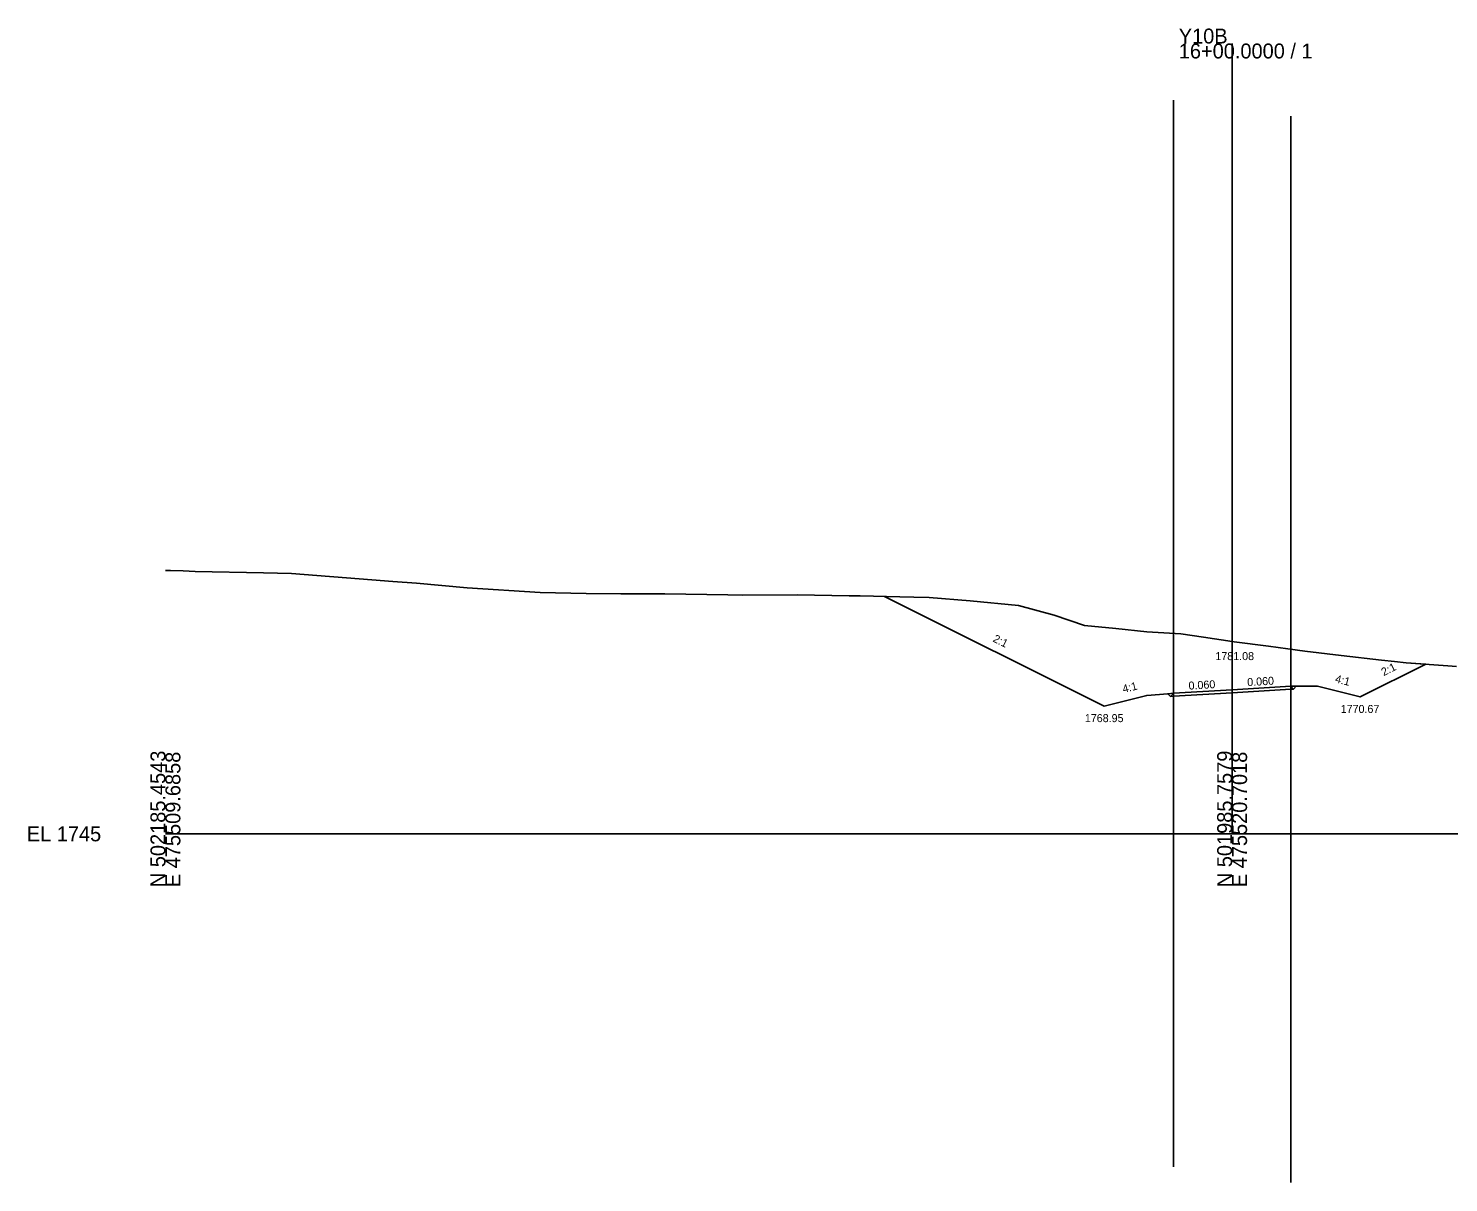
# Model space of a CAD drawing. Extents: x -26 to 1803, y -10 to 9558.
# Drawn here: x -25.7 to 240.6, y 5934.6 to 6151 of the extents above; entities that cross this region are included whole.
import ezdxf

# ---------------------------------------------------------------- set-up
doc = ezdxf.new("R2010")
doc.units = 0
for name, color, linetype in [('Exist Cross Section Cell', 7, 'Continuous'), ('Exist XS Center Line Elevation Label', 7, 'Continuous'), ('Exist XS Ground Line', 7, 'Continuous'), ('Prop XS Ditch Slope Text', 7, 'Continuous'), ('Prop XS Ditch Standard Text', 7, 'Continuous'), ('Prop XS Dump Level', 7, 'Continuous'), ('Prop XS Earthwork Shape', 7, 'Continuous'), ('Prop XS EOT Tick Mark', 7, 'Continuous'), ('Prop XS Finish Grade', 7, 'Continuous'), ('Prop XS Finish Grade Earthwork', 7, 'Continuous'), ('Prop XS Finish Grade Pavement', 7, 'Continuous'), ('Prop XS Hydro Typical Ditch Data', 7, 'Continuous'), ('Prop XS Pvmt Edge Slope', 7, 'Continuous'), ('Prop XS SE Text', 7, 'Continuous'), ('Prop XS Shoulder Borrow Shape', 7, 'Continuous'), ('Prop XS Side Slope Text', 7, 'Continuous'), ('Prop XS Subgrade Earthwork', 7, 'Continuous'), ('Scratch_Level_2', 7, 'Continuous')]:
    doc.layers.add(name, color=color, linetype=linetype)

msp = doc.modelspace()

# ---------------------------------------------------------------- linework, layer by layer
at = {"layer": 'Exist Cross Section Cell'}
for p, q in [((200, 6000), (200, 6148.21)), ((0, 6000), (200, 6000)), ((200, 6000), (400, 6000))]:
    msp.add_line(p, q, dxfattribs=at)
at = {"layer": 'Exist XS Ground Line'}
msp.add_lwpolyline([(0, 6049.4), (0.94, 6049.37), (3.32, 6049.34), (5.58, 6049.22), (18.36, 6048.95), (23.65, 6048.81), (38.73, 6047.61), (42.65, 6047.31), (47.09, 6046.98), (56.58, 6046.16), (70.27, 6045.28), (78.9, 6045.07), (85.36, 6045.01), (93.61, 6045.03), (105.48, 6044.84), (108.11, 6044.77), (118.45, 6044.8), (128.18, 6044.65), (130.28, 6044.65), (137.68, 6044.47), (140.3, 6044.41), (143.22, 6044.34), (150.91, 6043.69), (159.95, 6042.81), (166.66, 6040.98), (172.3, 6039.07), (178.22, 6038.5), (184.02, 6037.86), (190.38, 6037.48), (194.64, 6036.89), (200, 6036.08), (200.4, 6036.02), (206.83, 6035.22), (210.42, 6034.67), (213.62, 6034.26), (220.43, 6033.44), (228.04, 6032.6), (230.45, 6032.32), (232.61, 6032.1), (240.47, 6031.52), (242.1, 6031.37)], dxfattribs=at)
at = {"layer": 'Prop XS Dump Level'}
for p, q in [((189, 6026.35), (200, 6027.01)), ((200, 6027.01), (211, 6027.67))]:
    msp.add_line(p, q, dxfattribs=at)
at = {"layer": 'Prop XS Earthwork Shape'}
msp.add_lwpolyline([(232.61, 6032.1), (236.31, 6031.83), (224, 6025.67), (216, 6027.67), (212.02, 6027.67), (211.51, 6027.16), (211, 6027.13), (200, 6026.47), (189, 6025.81), (188.42, 6025.78), (187.93, 6026.27), (184, 6025.95), (176, 6023.95), (134.83, 6044.54), (137.68, 6044.47), (140.3, 6044.41), (143.22, 6044.34), (150.91, 6043.69), (159.95, 6042.81), (166.66, 6040.98), (172.3, 6039.07), (178.22, 6038.5), (184.02, 6037.86), (190.38, 6037.48), (194.64, 6036.89), (200, 6036.08), (200.4, 6036.02), (206.83, 6035.22), (210.42, 6034.67), (213.62, 6034.26), (220.43, 6033.44), (228.04, 6032.6), (230.45, 6032.32)], close=True, dxfattribs=at)
at = {"layer": 'Prop XS EOT Tick Mark'}
for p, q in [((189, 6026.35), (189, 6027.35)), ((211, 6027.67), (211, 6028.67))]:
    msp.add_line(p, q, dxfattribs=at)
at = {"layer": 'Prop XS Finish Grade'}
for p, q in [((189, 6026.35), (187.93, 6026.27)), ((211, 6027.67), (212.02, 6027.67))]:
    msp.add_line(p, q, dxfattribs=at)
at = {"layer": 'Prop XS Finish Grade Earthwork'}
for p, q in [((176, 6023.95), (134.83, 6044.54)), ((224, 6025.67), (236.31, 6031.83)), ((187.93, 6026.27), (184, 6025.95)), ((212.02, 6027.67), (216, 6027.67)), ((216, 6027.67), (224, 6025.67)), ((184, 6025.95), (176, 6023.95))]:
    msp.add_line(p, q, dxfattribs=at)
at = {"layer": 'Prop XS Finish Grade Pavement'}
for p, q in [((189, 6026.35), (200, 6027.01)), ((200, 6027.01), (211, 6027.67))]:
    msp.add_line(p, q, dxfattribs=at)
at = {"layer": 'Prop XS Hydro Typical Ditch Data'}
for p, q in [((176, 6023.95), (134.83, 6044.54)), ((224, 6025.67), (236.31, 6031.83)), ((216, 6027.67), (224, 6025.67)), ((184, 6025.95), (176, 6023.95))]:
    msp.add_line(p, q, dxfattribs=at)
at = {"layer": 'Prop XS Pvmt Edge Slope'}
for p, q in [((189, 6026.35), (188.42, 6025.78)), ((211, 6027.67), (211.51, 6027.16))]:
    msp.add_line(p, q, dxfattribs=at)
at = {"layer": 'Prop XS Shoulder Borrow Shape'}
for points in [[(189, 6026.35), (187.93, 6026.27), (188.42, 6025.78)], [(211, 6027.67), (212.02, 6027.67), (211.51, 6027.16)]]:
    msp.add_lwpolyline(points, close=True, dxfattribs=at)
at = {"layer": 'Prop XS Subgrade Earthwork'}
for p, q in [((188.42, 6025.78), (187.93, 6026.27)), ((200, 6026.47), (189, 6025.81)), ((211, 6027.13), (200, 6026.47)), ((211, 6027.13), (211.51, 6027.16)), ((211.51, 6027.16), (212.02, 6027.67)), ((189, 6025.81), (188.42, 6025.78))]:
    msp.add_line(p, q, dxfattribs=at)
at = {"layer": 'Scratch_Level_2'}
for p, q in [((189, 6137.56), (189, 5937.56)), ((211, 6134.6), (211, 5934.6))]:
    msp.add_line(p, q, dxfattribs=at)

# ---------------------------------------------------------------- texts
at = {"layer": 'Exist Cross Section Cell'}
for s, p in [('Y10B', (190, 6148.21)), ('16+00.0000 / 1', (190, 6145.41)), ('EL 1745', (-26, 5998.6))]:
    msp.add_text(s, height=2.8, dxfattribs=at).set_placement(p)
for s, p in [('N 502185.4543', (0, 5990)), ('N 501985.7579', (200, 5990)), ('E 475509.6858', (2.8, 5990)), ('E 475520.7018', (202.8, 5990))]:
    msp.add_text(s, height=2.8, rotation=90, dxfattribs=at).set_placement(p)
at = {"layer": 'Exist XS Center Line Elevation Label'}
msp.add_text('1781.08', height=1.5, dxfattribs=at).set_placement((196.86, 6032.58))
at = {"layer": 'Prop XS Ditch Slope Text'}
for rotation, p in [(345.9638, (219.21, 6028.42)), (14.0362, (179.64, 6026.41))]:
    msp.add_text('4:1', height=1.5, rotation=rotation, dxfattribs=at).set_placement(p)
at = {"layer": 'Prop XS Ditch Standard Text'}
for s, p in [('1770.67', (220.36, 6022.67)), ('1768.95', (172.39, 6020.95))]:
    msp.add_text(s, height=1.5, dxfattribs=at).set_placement(p)
at = {"layer": 'Prop XS Dump Level'}
for p in [(216, 6027.63), (184, 6025.91)]:
    msp.add_text('Case1', height=0.04, dxfattribs=at).set_placement(p)
at = {"layer": 'Prop XS SE Text'}
for p in [(191.88, 6027.03), (202.88, 6027.69)]:
    msp.add_text('0.060', height=1.5, rotation=3.4336, dxfattribs=at).set_placement(p)
at = {"layer": 'Prop XS Side Slope Text'}
for rotation, p in [(333.4349, (155.02, 6036.12)), (26.5651, (228.42, 6029.56))]:
    msp.add_text('2:1', height=1.5, rotation=rotation, dxfattribs=at).set_placement(p)

doc.saveas('drawing.dxf')
